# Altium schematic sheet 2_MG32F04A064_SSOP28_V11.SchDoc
size 330 x 228 mm; PageSetup: Record=PageOptions|CenterHorizontal=True|CenterVertical=True|PrintScale=0.86|XCorrection=1.00|YCorrection=1.00|PrintKind=0|BorderSize=5000000|LeftOffset=0|BottomOffset=0|Orientation=2|PaperLength=1000|PaperWidth=1000|Scale=100|PaperSource=7|PrintQuality=-4|MediaType=1|DitherType=10|PaperKind=A4 (210 x 297 mm)|PrintScaleMode=1
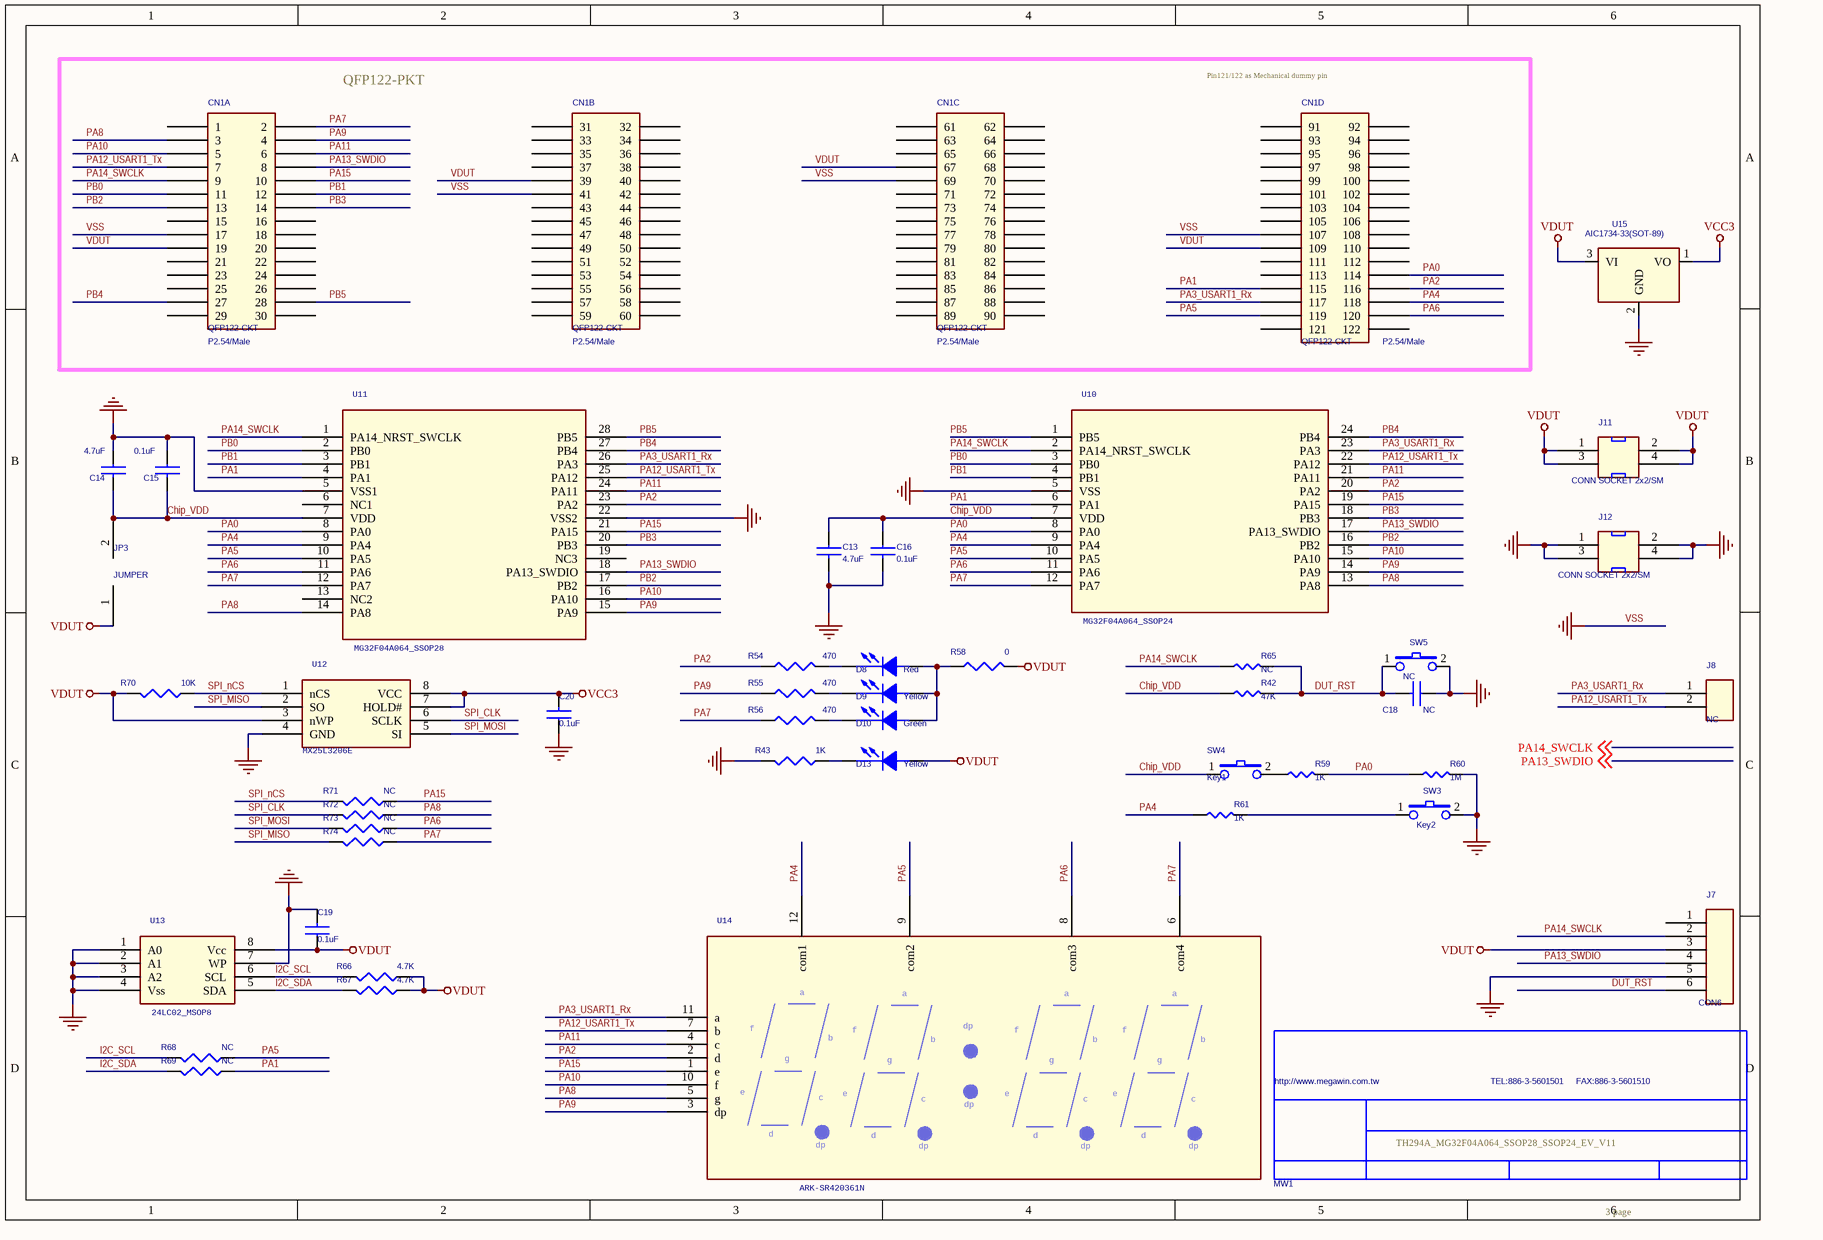
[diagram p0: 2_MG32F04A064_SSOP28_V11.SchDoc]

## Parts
C13  4.7uF  [0805C]
C14  4.7uF  [0805C]
C15  0.1uF  [0603C]
C16  0.1uF  [0603C]
C18  NC  [0603C]
C19  0.1uF  [0603C]
C20  0.1uF  [0603C]
CN1  QFP122-CKT  Package: P2.54/Male  [QFP122-P2.54-CKT]  (parts A,B,C,D of 4)
D8  Red  [0805D]
D9  Yellow  [0805D]
D10  Green  [0805D]
D13  Yellow  [0805D]
J7  CON6  [PS6P254]
J8  NC  [PS2P254]
J11  CONN SOCKET 2x2/SM  [PS2X2P254]
J12  CONN SOCKET 2x2/SM  [PS2X2P254]
JP3  JUMPER  [PS2P254]
MW1  OrgAddr3: TEL:886-3-5601501     FAX:886-3-5601510  [MEGAWIN_3_4_1]  (hidden comment: MW-A4)  (graphical)
R42  47K  [0603R]
R43  1K  [0603R]
R54  470  [0603R]
R55  470  [0603R]
R56  470  [0603R]
R58  0  [0603R]
R59  1K  [0603R]
R60  1M  [0603R]
R61  1K  [0603R]
R65  NC  [0603R]
R66  4.7K  [0603R]
R67  4.7K  [0603R]
R68  NC  [0603R]
R69  NC  [0603R]
R70  10K  [0603R]
R71  NC  [0603R]
R72  NC  [0603R]
R73  NC  [0603R]
R74  NC  [0603R]
SW3  Key2  [SW_T_2P]
SW4  Key1  [SW_T_2P]
SW5  NC  [SW_T_2P]
U10  MG32F04A064_SSOP24
U11  MG32F04A064_SSOP28
U12  MX25L3206E
U13  24LC02_MSOP8
U14  ARK-SR420361N  [7SEG_4A_12P254]
U15  AIC1734-33(SOT-89)  [SOT89]

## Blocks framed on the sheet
QFP122-PKT: CN1

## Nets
VCC3: C20.2 U12.7(HOLD#) U12.8(VCC) U15.1(VO)
VDUT: C19.1 CN1.19 CN1.39 CN1.67 CN1.109 D13.1(ANODE) J7.3 J11.1 J11.2 J11.3 J11.4 JP3.1 R58.2 R66.2 R67.2 R70.1 U12.3(nWP) U13.8(Vcc) U15.3(VI)
VSS: C13.2 C14.1 C15.1 C16.2 C18.1 C19.2 C20.1 CN1.17 CN1.41 CN1.69 CN1.107 J7.5 J12.1 J12.2 J12.3 J12.4 R43.1 R60.2 SW3.2 SW5.2 U10.5(VSS) U11.5(VSS1) U11.22(VSS2) U12.4(GND) U13.1(A0) U13.2(A1) U13.3(A2) U13.4(Vss) U13.7(WP) U15.2(GND)  [also labelled GND_POWER]
Chip_VDD: C13.1 C14.2 C15.2 C16.1 JP3.2 R42.1 SW4.1 U10.7(VDD) U11.7(VDD)
DUT_RST: C18.2 J7.6 R42.2 R65.2 SW5.1
I2C_SCL: R66.1 R68.1 U13.6(SCL)
I2C_SDA: R67.1 R69.1 U13.5(SDA)
PA0: CN1.114 R59.2 R60.1 U10.8(PA0) U11.8(PA0)
PA1: CN1.115 R69.2 U10.6(PA1) U11.4(PA1)
PA2: CN1.116 R54.1 U10.20(PA2) U11.23(PA2) U14.2(d)
PA3_USART1_Rx: CN1.117 J8.1 U10.23(PA3) U11.26(PA3) U14.11(a)
PA4: CN1.118 R61.1 U10.9(PA4) U11.9(PA4) U14.12(com1)
PA5: CN1.119 R68.2 U10.10(PA5) U11.10(PA5) U14.9(com2)
PA6: CN1.120 R73.2 U10.11(PA6) U11.11(PA6) U14.8(com3)
PA7: CN1.2 R56.1 R74.2 U10.12(PA7) U11.12(PA7) U14.6(com4)
PA8: CN1.3 R72.2 U10.13(PA8) U11.14(PA8) U14.5(g)
PA9: CN1.4 R55.1 U10.14(PA9) U11.15(PA9) U14.3(dp)
PA10: CN1.5 U10.15(PA10) U11.16(PA10) U14.10(f)
PA11: CN1.6 U10.21(PA11) U11.24(PA11) U14.4(c)
PA12_USART1_Tx: CN1.7 J8.2 U10.22(PA12) U11.25(PA12) U14.7(b)
PA13_SWDIO: CN1.8 J7.4 U10.17(PA13_SWDIO) U11.18(PA13_SWDIO) ; off-sheet PA13_SWDIO
PA14_SWCLK: CN1.9 J7.2 R65.1 U10.2(PA14_NRST_SWCLK) U11.1(PA14_NRST_SWCLK) ; off-sheet PA14_SWCLK
PA15: CN1.10 R71.2 U10.19(PA15) U11.21(PA15) U14.1(e)
PB0: CN1.11 U10.3(PB0) U11.2(PB0)
PB1: CN1.12 U10.4(PB1) U11.3(PB1)
PB2: CN1.13 U10.16(PB2) U11.17(PB2)
PB3: CN1.14 U10.18(PB3) U11.20(PB3)
PB4: CN1.27 U10.24(PB4) U11.27(PB4)
PB5: CN1.28 U10.1(PB5) U11.28(PB5)
SPI_CLK: R72.1 U12.6(SCLK)
SPI_MISO: R74.1 U12.2(SO)
SPI_MOSI: R73.1 U12.5(SI)
SPI_nCS: R70.2 R71.1 U12.1(nCS)
NetD8_1: D8.1(ANODE) D9.1(ANODE) D10.1(ANODE) R58.1
NetD8_2: D8.2(CATHODE) R54.2
NetD9_2: D9.2(CATHODE) R55.2
NetD10_2: D10.2(CATHODE) R56.2
NetD13_2: D13.2(CATHODE) R43.2
NetR59_1: R59.1 SW4.2
NetR61_2: R61.2 SW3.1

Not connected (* = marked no-connect by the designer): CN1 1 15 16 18 20 21 22 23 24 25 26 29 30 31 32 33 34 35 36 37 38 40 42 43 44 45 46 47 48 49 50 51 52 53 54 55 56 57 58 59 60 61 62 63 64 65 66 68 70 71 72 73 74 75 76 77 78 79 80 81 82 83 84 85 86 87 88 89 90 91 92 93 94 95 96 97 98 99 100 101 102 103 104 105 106 108 110 111 112 113 121 122; J7 1; U11 6(NC1) 13(NC2) 19(NC3)

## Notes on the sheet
- (near CN1) Pin121/122 as Mechanical dummy pin
- TH294A_MG32F04A064_SSOP28_SSOP24_EV_V11
- 3 page

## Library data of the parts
C13 = CAP NP_Dup1_C13: Origin: Altium
C14 = CAP NP_Dup1_C14: Origin: Altium
C15 C19 C20 = CAP NP_Dup1_C15: Origin: Altium
C16 = CAP NP_Dup1_C16: Origin: Altium
C18 = CAP NP_Dup1_C18: Origin: Altium
CN1 = QFP122-CKT_CN1: Origin: Altium
D8 = LED_D8: Origin: Altium
D9 = LED_D9: Origin: Altium
D10 = LED_D10: Origin: Altium
D13 = LED_D13: Origin: Altium
J7 = CON6_Dup1_J7: Origin: Altium
J8 = CON2_J8: Origin: Altium
J11 = CONN SOCKET 2x2/SM_J11: Origin: Altium
J12 = CONN SOCKET 2x2/SM_J12: Origin: Altium
JP3 = JUMPER_JP3: Origin: Altium
MW1 = MW_A4_2_MW1: Origin: Altium
R42 R65 = R_Dup3_R42: Origin: Altium
R43 R66-R74 = R_Dup4_R43: Origin: Altium
R54 = R_Dup4_R54: Origin: Altium
R55 = R_Dup4_R55: Origin: Altium
R56 = R_Dup4_R56: Origin: Altium
R58 = R_Dup4_R58: Origin: Altium
R59 = R_Dup3_R59: Origin: Altium
R60 = R_Dup3_R60: Origin: Altium
R61 = R_Dup3_R61: Origin: Altium
SW3 SW5 = SW TACT-SPST_SW3: Origin: Altium
SW4 = SW TACT-SPST_SW4: Origin: Altium
U13 = 24LC64_MSOP8
U14 = 7-segment_Common_Cathode
U15 = AIC1722-33_U1: Origin: Altium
